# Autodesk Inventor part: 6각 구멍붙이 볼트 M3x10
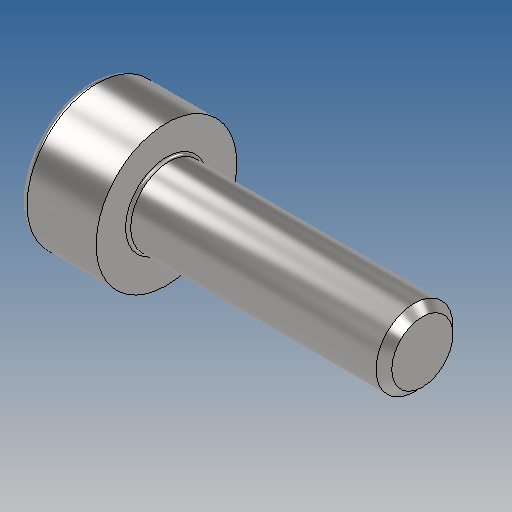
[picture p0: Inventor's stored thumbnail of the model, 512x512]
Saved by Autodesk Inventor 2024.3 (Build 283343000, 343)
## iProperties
Created: 2025-06
Part Number: 6각 구멍붙이 볼트 M3x10
Material: 강철, 연강
Description: 6각머리 태핑 나사
Document SubType Name: Modeling
Designer: user
Density: 7.85 g/cm^3
Appearance: 기본값
Sending System: Autodesk Inventor 2026
Preprocessor: ST-DEVELOPER v20.1
Author: jhkim
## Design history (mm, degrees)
node "6각 구멍붙이 볼트 M3x101"
node "솔리드1"
body "Solid1"
